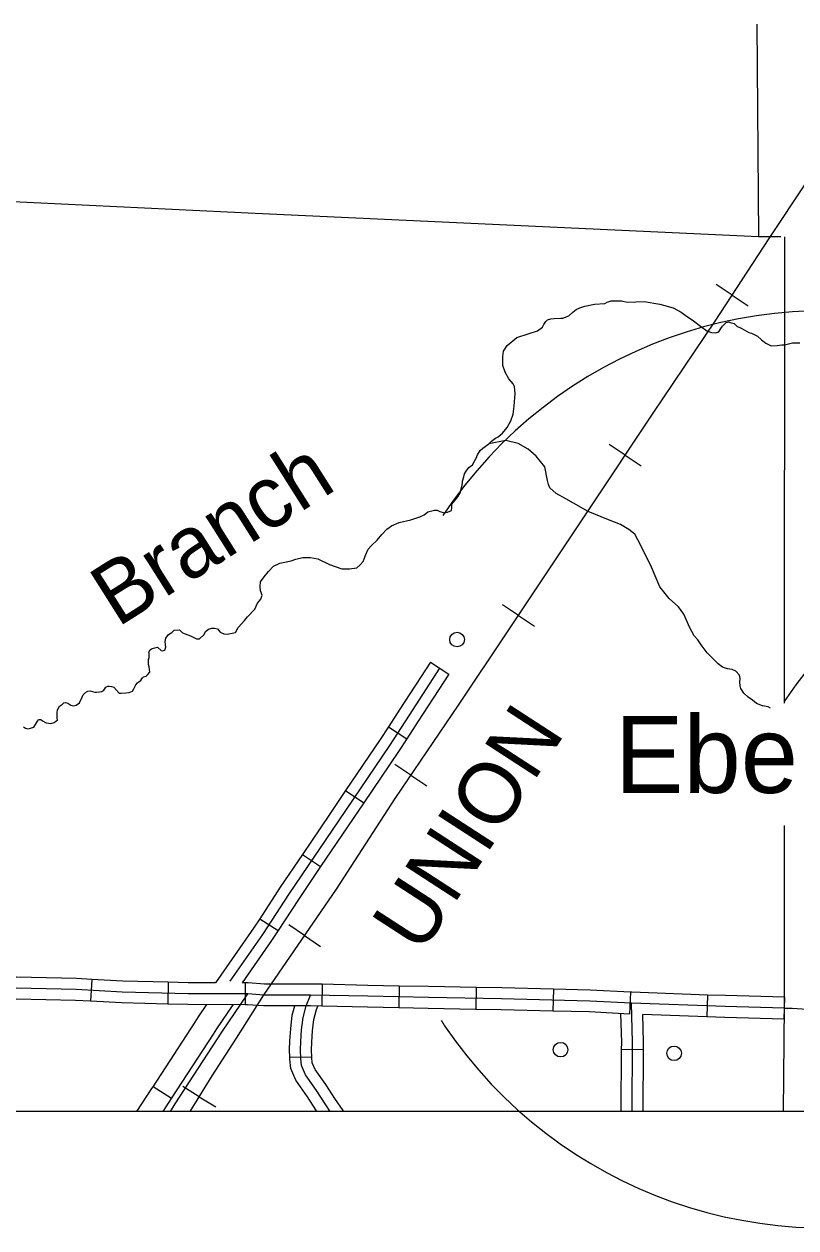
# Model space of a CAD drawing. Extents: x 22866 to 28196, y 1324810 to 1328105.
# Drawn here: x 25465.4 to 25592.4, y 1325736.3 to 1325934.5 of the extents above; entities that cross this region are included whole.
import ezdxf

# ---------------------------------------------------------------- set-up
doc = ezdxf.new("R2010")
doc.units = 0
for name, color, linetype in [('Level 24', 7, 'Continuous'), ('Level 31', 7, 'Continuous'), ('Level 32', 7, 'Continuous'), ('Level 35', 7, 'Continuous'), ('Level 4', 7, 'Continuous'), ('Level 40', 7, 'Continuous'), ('Level 45', 7, 'Continuous'), ('Level 5', 7, 'Continuous'), ('Level 56', 7, 'Continuous'), ('Level 63', 7, 'Continuous'), ('R_No Plot', 7, 'Continuous')]:
    doc.layers.add(name, color=color, linetype=linetype)

msp = doc.modelspace()

# ---------------------------------------------------------------- linework, layer by layer
at = {"layer": 'Level 31'}
msp.add_lwpolyline([(25515.76, 1325755.52), (25515.01, 1325756.6), (25513.5, 1325758.93), (25511.69, 1325761.53), (25511.04, 1325763.04), (25510.91, 1325764.23), (25510.87, 1325765.62), (25510.91, 1325767.02), (25511.04, 1325768.93), (25511.28, 1325770.99), (25511.79, 1325772.87), (25512.51, 1325774.67)], dxfattribs=at)
at = {"layer": 'Level 32'}
for p, q in [((25532.22, 1325829.44), (25535.24, 1325827.48)), ((25525.32, 1325818.81), (25528.34, 1325816.85)), ((25518.28, 1325808.31), (25521.26, 1325806.3)), ((25511.18, 1325797.82), (25514.16, 1325795.8)), ((25504.15, 1325787.23), (25507.16, 1325785.27)), ((25476.5, 1325777.24), (25476.3, 1325773.65)), ((25489.11, 1325776.76), (25489.01, 1325773.17)), ((25501.74, 1325776.67), (25501.73, 1325773.07)), ((25514.44, 1325776.43), (25514.36, 1325772.83)), ((25527.11, 1325776.15), (25527.03, 1325772.55)), ((25539.77, 1325775.91), (25539.71, 1325772.31)), ((25552.46, 1325775.63), (25552.37, 1325772.03)), ((25565.17, 1325775.12), (25564.98, 1325771.53)), ((25577.81, 1325774.67), (25577.68, 1325771.08)), ((25590.46, 1325774.32), (25590.37, 1325770.72)), ((25567.29, 1325765.65), (25563.69, 1325765.68))]:
    msp.add_line(p, q, dxfattribs=at)
for points in [[(25532.22, 1325829.44), (25527.2, 1325821.7), (25525.32, 1325818.81)], [(25533.73, 1325828.46), (25528.71, 1325820.72), (25525.48, 1325815.75), (25517.1, 1325803.35), (25509.01, 1325791.4), (25504.61, 1325784.65), (25499.24, 1325776.93)], [(25535.24, 1325827.48), (25530.22, 1325819.74), (25528.34, 1325816.85)], [(25525.32, 1325818.81), (25523.98, 1325816.75), (25518.28, 1325808.31)], [(25528.34, 1325816.85), (25526.98, 1325814.76), (25521.26, 1325806.3)], [(25518.28, 1325808.31), (25515.6, 1325804.36), (25511.18, 1325797.82)], [(25521.26, 1325806.3), (25518.59, 1325802.34), (25514.16, 1325795.8)], [(25511.18, 1325797.82), (25507.51, 1325792.4), (25504.15, 1325787.23)], [(25514.16, 1325795.8), (25510.51, 1325790.41), (25507.16, 1325785.27)], [(25504.15, 1325787.23), (25503.12, 1325785.65), (25496.87, 1325776.68)], [(25507.16, 1325785.27), (25506.11, 1325783.64), (25501.26, 1325776.67)], [(25476.5, 1325777.24), (25474, 1325777.38), (25464.13, 1325777.59), (25463.75, 1325777.6)], [(25489.11, 1325776.76), (25481.61, 1325776.96), (25476.5, 1325777.24)], [(25590.41, 1325772.52), (25580.72, 1325772.77), (25565.29, 1325773.31), (25558.46, 1325773.68), (25543.93, 1325774.04), (25531.89, 1325774.25), (25521.91, 1325774.46), (25512.51, 1325774.67), (25510.12, 1325774.67), (25504.85, 1325774.67), (25502.2, 1325774.87), (25492.35, 1325774.88), (25481.54, 1325775.16), (25473.93, 1325775.58), (25464.1, 1325775.79)], [(25496.87, 1325776.68), (25492.38, 1325776.68), (25489.11, 1325776.76)], [(25501.74, 1325776.67), (25501.26, 1325776.67)], [(25514.44, 1325776.43), (25512.53, 1325776.47), (25510.12, 1325776.47), (25504.92, 1325776.47), (25502.27, 1325776.67), (25501.74, 1325776.67)], [(25527.11, 1325776.15), (25521.95, 1325776.26), (25514.44, 1325776.43)], [(25539.77, 1325775.91), (25531.92, 1325776.05), (25527.11, 1325776.15)], [(25552.46, 1325775.63), (25543.97, 1325775.84), (25539.77, 1325775.91)], [(25565.17, 1325775.12), (25558.53, 1325775.48), (25552.46, 1325775.63)], [(25577.81, 1325774.67), (25565.38, 1325775.11), (25565.17, 1325775.12)], [(25476.3, 1325773.65), (25473.86, 1325773.78), (25464.07, 1325773.99), (25463.71, 1325774)], [(25489.01, 1325773.17), (25481.47, 1325773.36), (25476.3, 1325773.65)], [(25501.73, 1325773.07), (25492.33, 1325773.08), (25489.01, 1325773.17)], [(25514.36, 1325772.83), (25512.48, 1325772.87), (25510.12, 1325772.87), (25504.78, 1325772.87), (25502.13, 1325773.07), (25501.73, 1325773.07)], [(25565.41, 1325755.52), (25565.5, 1325766.9), (25565.29, 1325773.31)], [(25590.46, 1325774.32), (25580.78, 1325774.57), (25577.81, 1325774.67)], [(25527.03, 1325772.55), (25521.88, 1325772.66), (25514.36, 1325772.83)], [(25539.71, 1325772.31), (25531.85, 1325772.45), (25527.03, 1325772.55)], [(25552.37, 1325772.03), (25543.89, 1325772.24), (25539.71, 1325772.31)], [(25564.98, 1325771.53), (25558.39, 1325771.89), (25552.37, 1325772.03)], [(25563.69, 1325765.68), (25563.7, 1325766.87), (25563.55, 1325771.61)], [(25567.29, 1325765.65), (25567.3, 1325766.92), (25567.16, 1325771.45)], [(25577.68, 1325771.08), (25567.16, 1325771.45)], [(25590.41, 1325772.52), (25591.76, 1325772.49), (25594.21, 1325772.35)], [(25590.37, 1325770.72), (25580.67, 1325770.97), (25577.68, 1325771.08)], [(25563.61, 1325755.52), (25563.69, 1325765.68)], [(25567.21, 1325755.52), (25567.29, 1325765.65)]]:
    msp.add_lwpolyline(points, dxfattribs=at)
at = {"layer": 'Level 35'}
for points in [[(25540.88, 1325864.69), (25541.82, 1325865.37), (25542.29, 1325865.86), (25542.92, 1325866.31), (25543.36, 1325866.57), (25544.1, 1325867.17), (25544.88, 1325868.06), (25545.45, 1325869.19), (25545.87, 1325870.26), (25546, 1325871.62), (25546.16, 1325873.66), (25546.06, 1325874.84), (25545.85, 1325875.26), (25545.14, 1325876.07), (25544.51, 1325877.17), (25544.15, 1325878.3), (25544.12, 1325879.76), (25544.25, 1325880.65), (25544.83, 1325881.57), (25546.45, 1325882.88), (25548.46, 1325883.53), (25549.86, 1325884), (25550.68, 1325884.58), (25550.88, 1325885.02), (25551.2, 1325885.52), (25551.51, 1325885.81), (25552.03, 1325885.97), (25552.58, 1325886.02), (25553.66, 1325886.07), (25554, 1325886.07), (25555.02, 1325886.46), (25555.67, 1325887.06), (25556.19, 1325887.48), (25556.82, 1325887.8), (25557.63, 1325888.06), (25559.22, 1325888.37), (25560.9, 1325888.48)], [(25560.9, 1325888.48), (25561.31, 1325888.73), (25561.94, 1325888.94), (25562.62, 1325888.96), (25563.64, 1325888.91), (25564.61, 1325888.73), (25566.04, 1325888.76), (25567.4, 1325888.81), (25569.97, 1325888.39), (25572.14, 1325887.79), (25573.47, 1325887.08), (25574.15, 1325886.56), (25575.53, 1325885.62), (25576.66, 1325884.78), (25577.7, 1325883.97), (25578.49, 1325883.7), (25579.12, 1325883.68), (25579.66, 1325883.82), (25580.02, 1325884.4), (25580.29, 1325884.76), (25580.6, 1325885.11), (25580.91, 1325885.34), (25581.33, 1325885.45), (25581.57, 1325885.39), (25582.19, 1325885.18), (25582.64, 1325884.79), (25583.45, 1325884.37), (25584.62, 1325883.72), (25585.07, 1325883.61), (25585.62, 1325883.35), (25586.04, 1325883.12), (25586.72, 1325882.49), (25587.42, 1325881.96), (25588.28, 1325881.55), (25589.25, 1325881.6), (25590.06, 1325881.68), (25590.48, 1325881.7), (25591.79, 1325882.04), (25592.23, 1325882.02), (25592.99, 1325882.02)], [(25513.71, 1325846.45), (25515.6, 1325845.52), (25517.67, 1325844.81), (25518.9, 1325844.84), (25520.13, 1325844.97), (25520.68, 1325845.49), (25521.17, 1325846.04), (25521.33, 1325846.49), (25521.59, 1325847.2), (25522.01, 1325848.03), (25522.51, 1325848.64), (25523.47, 1325849.52), (25524.26, 1325850.49), (25525.07, 1325851.36), (25525.85, 1325851.88), (25527.08, 1325852.46), (25528.99, 1325852.9), (25530.47, 1325853.38), (25531.18, 1325853.7), (25531.81, 1325854.19), (25532.49, 1325854.38), (25532.88, 1325854.48), (25533.32, 1325854.48), (25533.77, 1325854.25), (25534.53, 1325854.06), (25535.02, 1325854.14), (25535.68, 1325854.43), (25535.76, 1325854.87), (25535.76, 1325855.48), (25536.3, 1325856.13), (25536.75, 1325856.68), (25537.14, 1325857.31), (25537.4, 1325858.38), (25537.53, 1325858.98), (25537.53, 1325859.24), (25537.72, 1325859.98), (25537.82, 1325860.45), (25538.11, 1325860.92), (25538.55, 1325861.49), (25539.13, 1325861.96), (25539.76, 1325863.06), (25539.99, 1325863.61), (25540.44, 1325864.29), (25540.88, 1325864.69)], [(25551.48, 1325859.36), (25551.06, 1325861.61), (25549.65, 1325863.34), (25548.29, 1325864.49), (25546.67, 1325865.43), (25544.63, 1325865.95), (25541.82, 1325865.37)], [(25573.03, 1325838.54), (25571.51, 1325839.94), (25569.99, 1325841.88), (25568.58, 1325845.12), (25566.85, 1325848.68), (25565.86, 1325850.52), (25564.87, 1325851.3), (25563.51, 1325852.09), (25561.52, 1325852.87), (25558.17, 1325854.28), (25555.77, 1325855.64), (25554.51, 1325856.32), (25552.94, 1325857.21), (25551.9, 1325858.16), (25551.64, 1325858.68), (25551.48, 1325859.36)], [(25487.35, 1325831.93), (25487.93, 1325831.38), (25488.14, 1325831.33), (25488.56, 1325831.43), (25488.72, 1325831.9), (25488.66, 1325832.32), (25488.61, 1325832.84), (25488.72, 1325833.42), (25489.13, 1325833.99), (25489.66, 1325834.36), (25490.08, 1325834.73), (25490.96, 1325834.78), (25491.43, 1325834.31), (25492.74, 1325833.78), (25493.74, 1325833.31), (25494.26, 1325833.31), (25494.99, 1325833.99), (25495.2, 1325834.52), (25495.72, 1325834.88), (25496.25, 1325835.04), (25496.72, 1325835.04), (25497.19, 1325834.94), (25497.66, 1325834.41), (25498.23, 1325834.1), (25498.81, 1325834.05), (25500.17, 1325834.36), (25500.58, 1325835.15), (25501.63, 1325836.3), (25502.15, 1325836.92), (25503.36, 1325838.18), (25503.77, 1325839.18), (25504.35, 1325839.8), (25504.56, 1325840.48), (25504.3, 1325841.22), (25504.24, 1325841.9), (25504.3, 1325842.68), (25504.87, 1325843.52), (25505.6, 1325844.36), (25506.39, 1325845.25), (25507.43, 1325845.77), (25509.32, 1325846.14), (25510.1, 1325846.4), (25511.25, 1325846.66), (25512.51, 1325846.66), (25513.71, 1325846.45)], [(25588.19, 1325821.9), (25587.78, 1325822.1), (25586.86, 1325822.26), (25585.9, 1325822.68), (25585.22, 1325823.18), (25584.51, 1325823.72), (25583.81, 1325824.33), (25583.31, 1325825.12), (25583.18, 1325825.56), (25583.15, 1325826.14), (25583.18, 1325826.79), (25583.07, 1325827.32), (25582.5, 1325827.95), (25581.85, 1325828.23), (25581.11, 1325828.34), (25580.3, 1325828.63), (25579.57, 1325829.18), (25578.68, 1325830.07), (25577.74, 1325830.98), (25576.77, 1325832.32), (25576.22, 1325833.13), (25575.62, 1325833.78), (25574.86, 1325835.22), (25574.5, 1325835.98), (25573.92, 1325837.34), (25573.03, 1325838.54)], [(25481, 1325824.37), (25481.34, 1325824.34), (25482.13, 1325824.39), (25482.65, 1325824.45), (25483.2, 1325824.68), (25483.46, 1325825.05), (25483.77, 1325825.75), (25484.06, 1325826.04), (25484.32, 1325826.28), (25484.56, 1325826.46), (25484.74, 1325826.7), (25484.87, 1325826.88), (25485.03, 1325827.04), (25485.45, 1325827.17), (25485.71, 1325827.38), (25486.05, 1325827.79), (25485.99, 1325828.24), (25485.97, 1325828.71), (25485.86, 1325829.05), (25485.84, 1325829.5), (25485.86, 1325829.89), (25485.94, 1325830.25), (25485.94, 1325830.65), (25485.94, 1325830.88), (25485.92, 1325831.12), (25486.1, 1325831.48), (25486.33, 1325831.64), (25486.65, 1325831.77), (25487.35, 1325831.93)], [(25465.27, 1325818.83), (25465.61, 1325818.57), (25465.98, 1325818.49), (25466.42, 1325818.57), (25466.97, 1325818.77), (25467.28, 1325819.22), (25467.57, 1325819.72), (25467.75, 1325819.95), (25467.86, 1325820), (25468.15, 1325820), (25468.41, 1325819.8), (25469.04, 1325819.46), (25469.79, 1325819.38), (25470.32, 1325819.51), (25470.63, 1325819.72), (25470.87, 1325819.9), (25470.84, 1325820.29), (25470.84, 1325820.66), (25470.84, 1325821.18), (25470.89, 1325821.6), (25471.18, 1325822.2), (25471.68, 1325822.57), (25471.91, 1325822.75), (25472.2, 1325822.8), (25472.59, 1325822.73), (25473.06, 1325822.39), (25473.5, 1325822.26), (25473.94, 1325822.36), (25474.47, 1325822.78), (25474.96, 1325823.67), (25475.12, 1325824.06), (25475.51, 1325824.45), (25475.88, 1325824.71), (25476.24, 1325824.73), (25477.03, 1325824.52), (25477.29, 1325824.52), (25477.81, 1325824.55), (25478.15, 1325824.65), (25478.49, 1325824.86), (25478.7, 1325825.18), (25478.83, 1325825.34), (25479.17, 1325825.49), (25479.35, 1325825.52), (25479.75, 1325825.47), (25480.16, 1325825.36), (25480.61, 1325824.84), (25481, 1325824.37)]]:
    msp.add_lwpolyline(points, dxfattribs=at)
at = {"layer": 'Level 4'}
msp.add_lwpolyline([(25589.87, 1325899.48), (25586.22, 1325899.46), (25503.41, 1325903.31), (25462.45, 1325905.3), (25458.7, 1325905.28), (25404.9, 1325905.01)], dxfattribs=at)
at = {"layer": 'Level 40'}
for p, q in [((25581.88, 1325889.87), (25579.23, 1325891.6)), ((25581.88, 1325889.87), (25584.53, 1325888.13)), ((25564.26, 1325863.53), (25561.62, 1325865.29)), ((25564.26, 1325863.53), (25566.89, 1325861.78)), ((25546.71, 1325837.15), (25544.07, 1325838.91)), ((25546.71, 1325837.15), (25549.35, 1325835.4)), ((25529.03, 1325810.86), (25526.4, 1325812.63)), ((25529.03, 1325810.86), (25531.65, 1325809.08)), ((25511.53, 1325784.45), (25508.91, 1325786.24)), ((25511.53, 1325784.45), (25514.14, 1325782.66)), ((25494.2, 1325757.93), (25491.5, 1325759.59)), ((25494.2, 1325757.93), (25496.9, 1325756.26))]:
    msp.add_line(p, q, dxfattribs=at)
msp.add_lwpolyline([(25492.71, 1325755.52), (25496.31, 1325761.34), (25500.34, 1325767.54), (25504.76, 1325774.59), (25516.78, 1325792.11), (25526.44, 1325807.02), (25536.83, 1325822.38), (25545.04, 1325834.64), (25558.16, 1325854.38), (25568.88, 1325870.46), (25579.1, 1325885.61), (25587.97, 1325899.18), (25600.25, 1325917.68), (25612.11, 1325935.34), (25615.88, 1325940.99), (25624.6, 1325954.01), (25629.96, 1325961.87), (25634.64, 1325968.94)], dxfattribs=at)
at = {"layer": 'Level 45'}
for p, q in [((25512.7, 1325764.44), (25509.1, 1325764.36)), ((25489.63, 1325757.61), (25486.6, 1325759.57))]:
    msp.add_line(p, q, dxfattribs=at)
for points in [[(25587.97, 1325899.18), (25600.25, 1325917.68), (25612.11, 1325935.34), (25615.88, 1325940.99), (25624.6, 1325954.01)], [(25545.04, 1325834.64), (25558.16, 1325854.38), (25568.88, 1325870.46), (25579.1, 1325885.61), (25587.97, 1325899.18)], [(25504.76, 1325774.59), (25516.78, 1325792.11), (25526.44, 1325807.02), (25536.83, 1325822.38), (25545.04, 1325834.64)], [(25489.45, 1325755.52), (25490.25, 1325756.74), (25497.91, 1325768.54), (25502.2, 1325774.87)], [(25492.71, 1325755.52), (25496.31, 1325761.34), (25500.34, 1325767.54), (25504.76, 1325774.59)], [(25493.5, 1325770.21), (25494.07, 1325771.09), (25495.42, 1325773.08)], [(25496.52, 1325768.25), (25497.07, 1325769.1), (25499.76, 1325773.07)], [(25509.1, 1325764.36), (25509.07, 1325765.62), (25509.11, 1325767.1), (25509.25, 1325769.1), (25509.51, 1325771.33), (25509.93, 1325772.87)], [(25512.7, 1325764.44), (25512.67, 1325765.62), (25512.7, 1325766.93), (25512.84, 1325768.77), (25513.05, 1325770.64), (25513.51, 1325772.3), (25513.72, 1325772.84)], [(25486.6, 1325759.57), (25493.5, 1325770.21)], [(25489.62, 1325757.61), (25496.52, 1325768.25)], [(25513.57, 1325755.52), (25513.51, 1325755.6), (25512.01, 1325757.93), (25510.11, 1325760.65), (25509.28, 1325762.57), (25509.11, 1325764.11), (25509.1, 1325764.36)], [(25517.92, 1325755.52), (25517.87, 1325755.65), (25516.5, 1325757.61), (25515, 1325759.93), (25513.27, 1325762.41), (25512.8, 1325763.5), (25512.7, 1325764.36), (25512.7, 1325764.44)], [(25483.91, 1325755.52), (25486.4, 1325759.27), (25486.6, 1325759.57)], [(25488.24, 1325755.52), (25489.63, 1325757.61)]]:
    msp.add_lwpolyline(points, dxfattribs=at)
at = {"layer": 'Level 5'}
for points in [[(25585.93, 1325934.49), (25586.22, 1325899.46)], [(25590.51, 1325899.48), (25590.45, 1325822.69)], [(25590.44, 1325802.56), (25590.42, 1325772.88)], [(25590.42, 1325772.88), (25590.24, 1325755.52)]]:
    msp.add_lwpolyline(points, dxfattribs=at)
at = {"layer": 'Level 56'}
for centre in [(25536.61, 1325833.18), (25553.64, 1325765.67), (25572.33, 1325765.07)]:
    msp.add_circle(centre, 1.2, dxfattribs=at)
at = {"layer": 'Level 63'}
for centre, radius, start, end in [((25597.17, 1325811.83), 75.5, 213.9903, 146.4237), ((25646.75, 1325785.63), 67.58, 333.5402, 146.4237), ((25597.17, 1325811.83), 75.5, 213.202, 213.9903)]:
    msp.add_arc(centre, radius, start, end, dxfattribs=at)
at = {"layer": 'R_No Plot'}
msp.add_lwpolyline([(24815.02, 1326581.62), (26086.71, 1326581.62), (26086.71, 1325755.52), (24815.02, 1325755.52)], close=True, dxfattribs=at)
msp.add_lwpolyline([(24815.02, 1326581.62), (26086.71, 1326581.62), (26086.71, 1325755.52), (24815.02, 1325755.52)], close=True, dxfattribs=at)

# ---------------------------------------------------------------- texts
at = {"layer": 'Level 24'}
msp.add_text('Ebenezer', height=12.674, dxfattribs=at).set_placement((25562.56, 1325807.93))
at = {"layer": 'Level 35'}
msp.add_text('Branch', height=10.139, rotation=32.2681, dxfattribs=at).set_placement((25480.73, 1325835.09))
at = {"layer": 'Level 40'}
msp.add_text('UNION', height=10.139, rotation=57.0055, dxfattribs=at).set_placement((25530.69, 1325781.16))

doc.saveas('drawing.dxf')
